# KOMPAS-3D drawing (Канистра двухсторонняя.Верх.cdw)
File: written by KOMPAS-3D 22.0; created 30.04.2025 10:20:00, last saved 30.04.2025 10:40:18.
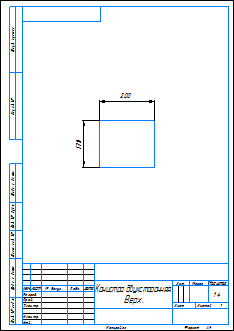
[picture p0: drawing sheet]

Sheet 1: A4, portrait

Document properties: Автор: Admin; Наименование: Канистра двухсторонняя. Верх; Полное имя файла: D:\28.11.2016\3D модели\Абилимпикс\2025\Канистра двухсторонняя\Канистра двухсторонняя.Верх.cdw

Title block, sheet 1: Наименование: Канистра двухсторонняя. / Верх.; scale: 1:4; Количество листов документа: 1; Форматы листов документа: A4; stored path: D:\28.11.2016\3D модели\Абилимпикс\2025\Канистра двухсторонняя\Канистра двухсторонняя.Боковина.cdw

Dimensions and other numbers on the sheet: 200; 170; 1:4; 1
